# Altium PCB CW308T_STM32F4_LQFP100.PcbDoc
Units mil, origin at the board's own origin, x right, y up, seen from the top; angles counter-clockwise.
Board outline 2060 x 2540 mil, 2 copper layers (Top Layer, Bottom Layer); 19 components, 32 nets, 206 pads, 96 vias.
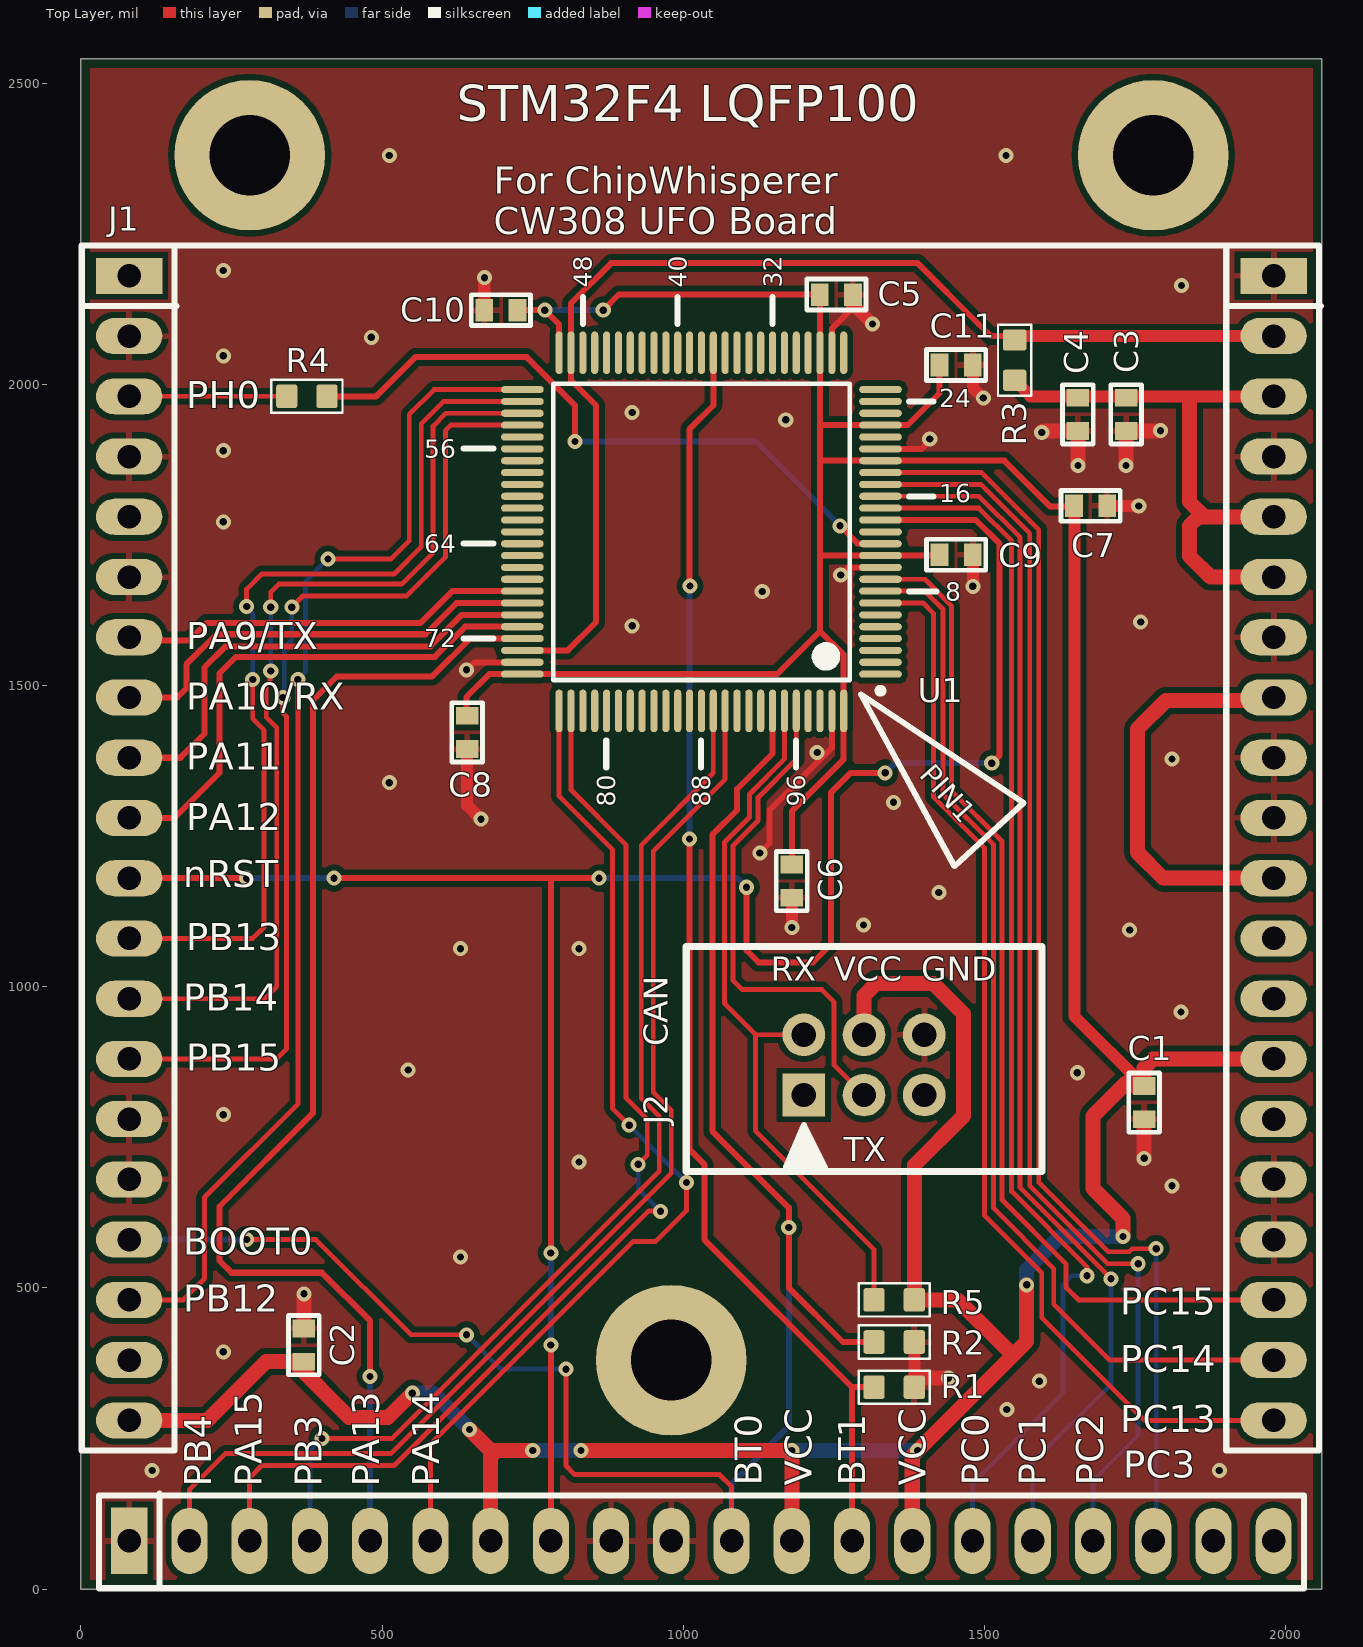
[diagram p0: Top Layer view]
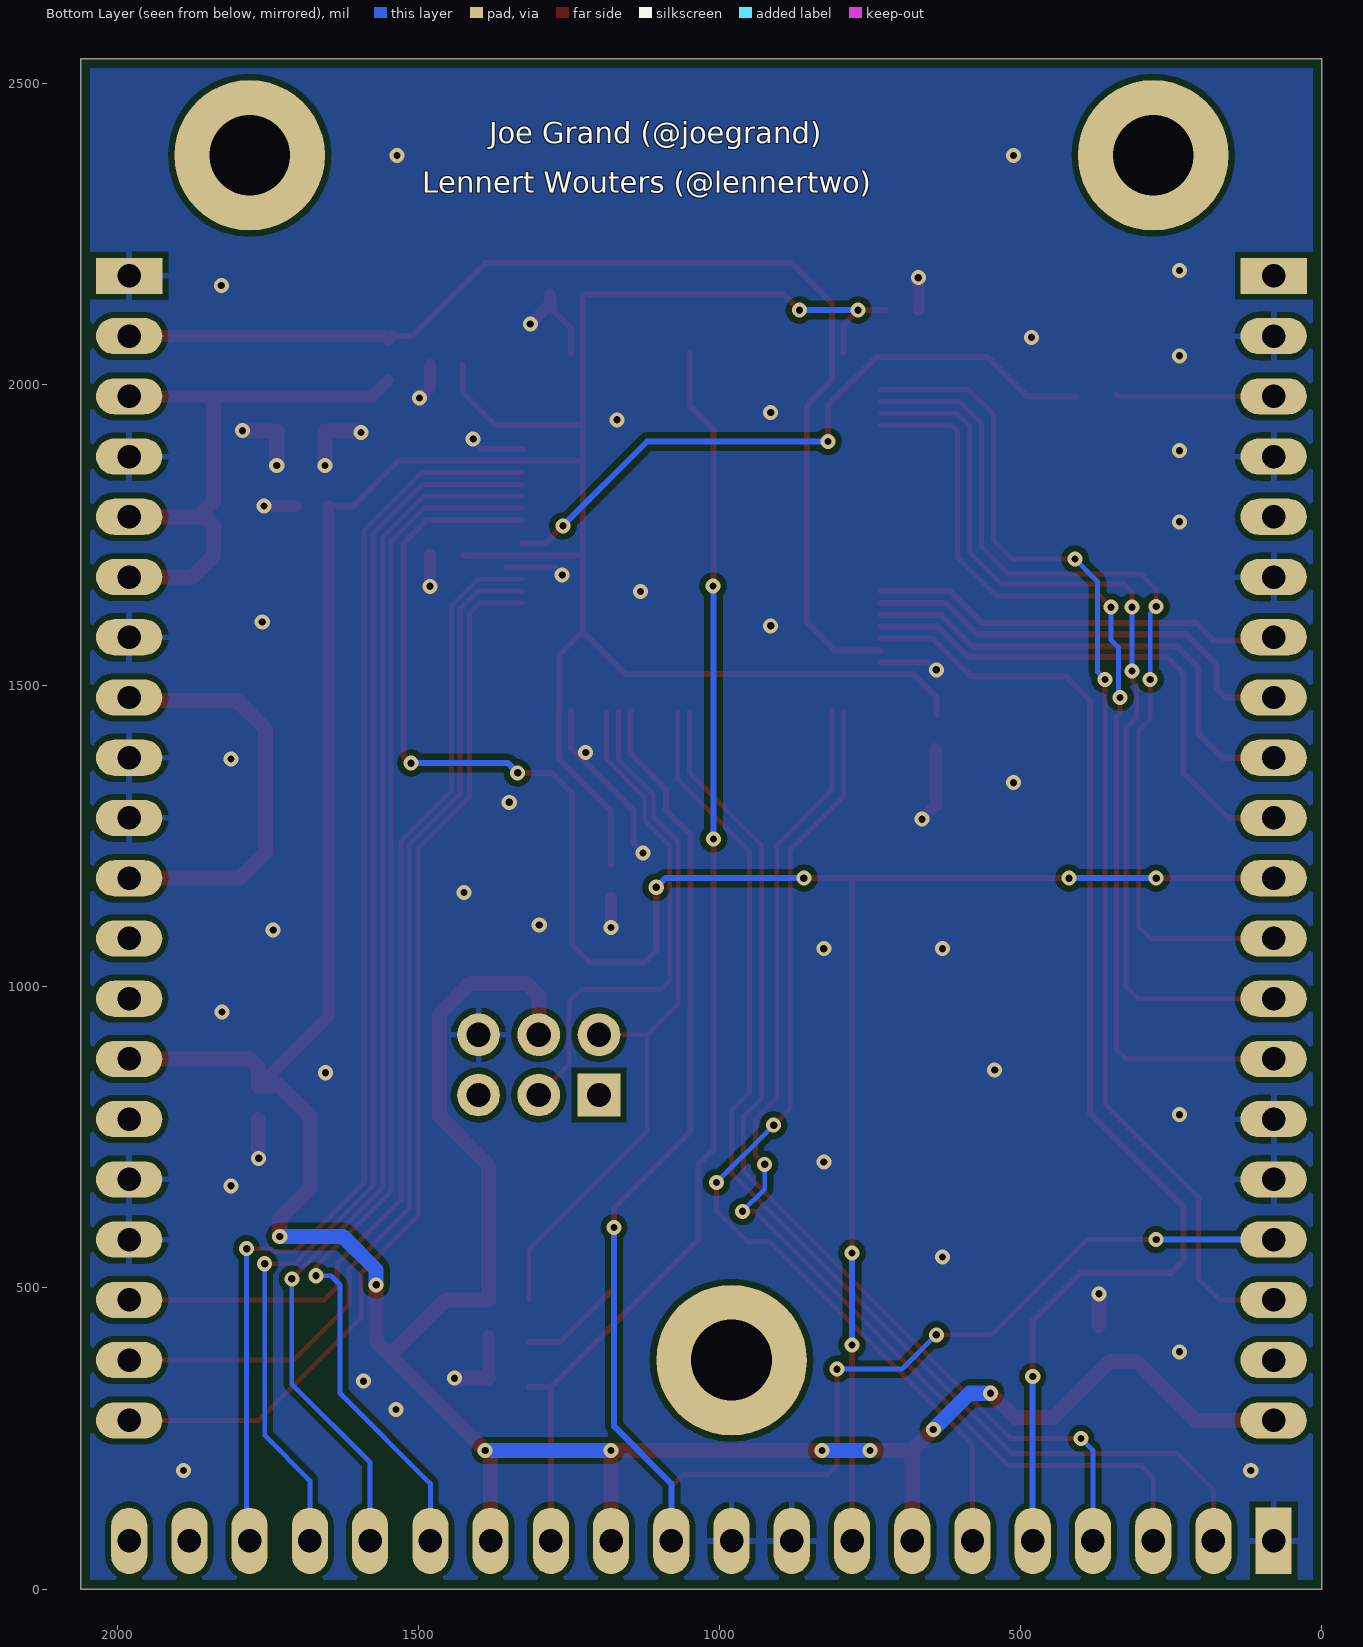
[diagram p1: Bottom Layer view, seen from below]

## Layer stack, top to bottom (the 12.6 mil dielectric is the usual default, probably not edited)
Top Solder: solder mask 0.4, Solder Resist, Dk 3.5
Top Layer: signal copper 1.4
Dielectric 1: dielectric 12.6, FR-4, Dk 4.8
Bottom Layer: signal copper 1.4
Bottom Solder: solder mask 0.4, Solder Resist, Dk 3.5

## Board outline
0,0 2060,0 2060,2540 0,2540

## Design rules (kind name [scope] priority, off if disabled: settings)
BoardOutlineClearance [All] p1: gap=15 ignorepadtopadclearanceinfootprint=FALSE except(0: Arc-SplitContinuation Track-SplitContinuation SMDPad-SplitContinuation THPad-SplitContinuation Via-SplitContinuation Fill-SplitContinuation Poly-SplitContinuation Region-SplitContinuation Text-SplitContinuation)
Clearance Clearance_1 [InPolygon] p1: gap=10 ignorepadtopadclearanceinfootprint=FALSE
Clearance [All] p2: gap=6 ignorepadtopadclearanceinfootprint=FALSE except(0: Arc-Hole Track-Hole SMDPad-Hole THPad-Hole Via-Hole Fill-Hole Poly-Hole Region-Hole Text-Hole)
HoleSize [All] p1: absolutevalues=TRUE maxlimit=200 minlimit=1 maxpercent=80.000 minpercent=20.000
MinimumSolderMaskSliver [All] p1: minsoldermaskwidth=5
PasteMaskExpansion PasteMaskExpansion_SJ [InComponent('SJ2')] p1: expansion=-200 // Disable SJ shorts
PasteMaskExpansion PasteMaskExpansion_TQFP [InComponent('U1')] p2: expansion=-99999 usepaste=FALSE
PasteMaskExpansion [All] p3: expansion=0
PlaneConnect PlaneConnect_viaDirect [IsVia] p1: planeconnectstyle=Direct reliefexpansion=20 reliefentries=4 reliefconductorwidth=10 reliefairgap=10
PlaneConnect [All] p2: planeconnectstyle=Relief reliefexpansion=20 reliefentries=4 reliefconductorwidth=10 reliefairgap=10
PolygonConnect PolygonConnect_viaDirect [All vs isVia] p1: connectstyle=Direct reliefconductorwidth=10 reliefentries=4 polygonreliefangle="90 Angle" airgapwidth=10
PolygonConnect [All] p2: connectstyle=Relief reliefconductorwidth=10 reliefentries=4 polygonreliefangle="90 Angle" airgapwidth=10
RoutingVias [All] p1: holewidth=12 width=25 viastyle="Through Hole" minholewidth=12 minwidth=25 maxholewidth=28 maxwidth=50
SilkToSilkClearance [All] p1: silktosilkclearance=5
SilkToSolderMaskClearance [IsPad] p1: minsilkscreentomaskgap=2.9 clearancetoexposedcopper=TRUE
SolderMaskExpansion U1 [InComponent('U1')] p1: expansion=2.5 istentingtop=FALSE
SolderMaskExpansion [All] p2: expansion=4 istentingtop=FALSE
SupplyNets "Schematic Supply Nets_1" [InNet('VCC')] p1: voltage=0.000
SupplyNets "Schematic Supply Nets" [InNet('GND')] p2: voltage=0.000
Width [All] p1: maxlimit=100 minlimit=6 preferedwidth=8 minimp=50.000000 maximp=50.000000 favimp=50.000000
24 further rules are at their usual default settings.

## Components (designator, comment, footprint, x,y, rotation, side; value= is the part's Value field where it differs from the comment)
C1 "100n" CAPC0603_M#1 1765,807.44 r270 top
C2 "100n" CAPC0603_M#1 370,405 r90 top
C3 "2u2" CAPC0603_M#1 1735,1950 r270 top
C4 "100n" CAPC0603_M#1 1655,1950 r270 top
C5 "100n" CAPC0603_M#2 1254,2149 r0 top
C6 "100n" CAPC0603_M#2 1180,1175 r270 top
C7 "100n" CAPC0603_M#2 1676,1798 r0 top
C8 "100n" CAPC0603_M#2 641,1422 r270 top
C9 "100n" CAPC0603_M#2 1453,1717 r0 top
C10 "100n" CAPC0603_M#2 697,2123 r180 top
C11 "100n" CAPC0603_M#1 1453,2032 r0 top
J1 "CW308_TARGETCON" CW308_TBOARD_CONN 80,2180 r0 top locked
J2 "HDR" HDR_6PIN_2ROW_SHROUD 1300,870 r90 top
R1 "10k" RESC1608X55N 1350,335 r0 top
R2 "10k" RESC1608X55N 1350,410 r0 top
R3 "10R" RESC1608X55N 1550,2040 r270 top
R4 "51R" RESC1608X55N 375,1980 r180 top value=100R
R5 "10k" RESC1608X55N 1350,480 r0 top
U1 "STM32F427VIT6" STM-LQFP100_N 1030,1755 r180 top locked

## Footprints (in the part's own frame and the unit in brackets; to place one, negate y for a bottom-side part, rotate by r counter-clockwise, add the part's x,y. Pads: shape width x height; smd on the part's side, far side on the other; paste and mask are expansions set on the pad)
CAPC0603_M#1 [mm]
  rect 0.75x0.95 smd: 1(-0.7,0) 2(0.7,0)
  silkscreen extent -1.25,-0.65 1.25,0.65, body extent -0.85,-0.45 0.85,0.45, height 0.9
CAPC0603_M#2 [mm]
  rect 0.75x0.95 smd paste-2539.97: 1(-0.7,0) 2(0.7,0)
  silkscreen extent -1.25,-0.65 1.25,0.65, body extent -0.85,-0.45 0.85,0.45, height 0.9
CW308_TBOARD_CONN [mil]
  rect 110x60 hole 39: A1(0,0) C1(1900,0)
  oval 110x60 hole 39: A2(0,-100) A3(0,-200) A4(0,-300) A5(0,-400) A6(0,-500) A7(0,-600) A8(0,-700) A9(0,-800) A10(0,-900) A11(0,-1000) A12(0,-1100) A13(0,-1200) A14(0,-1300) A15(0,-1400) A16(0,-1500) A17(0,-1600) A18(0,-1700) A19(0,-1800) A20(0,-1900) C2(1900,-100) C3(1900,-200) C4(1900,-300) C5(1900,-400) C6(1900,-500) C7(1900,-600) C8(1900,-700) C9(1900,-800) C10(1900,-900) C11(1900,-1000) C12(1900,-1100) C13(1900,-1200) C14(1900,-1300) C15(1900,-1400) C16(1900,-1500) C17(1900,-1600) C18(1900,-1700) C19(1900,-1800) C20(1900,-1900)
  rect 60x110 hole 39: B1(0,-2100)
  oval 60x110 hole 39: B2(100,-2100) B3(200,-2100) B4(300,-2100) B5(400,-2100) B6(500,-2100) B7(600,-2100) B8(700,-2100) B9(800,-2100) B10(900,-2100) B11(1000,-2100) B12(1100,-2100) B13(1200,-2100) B14(1300,-2100) B15(1400,-2100) B16(1500,-2100) B17(1600,-2100) B18(1700,-2100) B19(1800,-2100) B20(1900,-2100)
  round 250 hole 134: MH1(200,200) MH2(900,-1800) MH2(1700,200)
  silkscreen extent -79,-2179 1979,50, body extent -50,-2149 1950,50, height 48
HDR_6PIN_2ROW_SHROUD [mm] "6-pin header, male, with shroud"
  rect 1.8x1.8 hole 1.02: 1(-1.27,2.54)
  round 1.8 hole 1.02: 2(1.27,2.54) 3(-1.27,0) 4(1.27,0) 5(-1.27,-2.54) 6(1.27,-2.54)
  silkscreen extent -4.5,-7.5 5,7.5, body extent -4.44,-7.41 4.83,7.42, height 9.32
RESC1608X55N [mm] "Chip Resistor, Body 1.6x0.8mm, EIA 0603, IPC Medium Density"
  round 0.254 on Mech15: 0(0,0)
  rrect25% 0.9x1 smd: 1(-0.85,0) 2(0.85,0)
  Top Layer pour cut-out: -0.6,0.5 -0.4,0.7 0.4,0.7 0.6,0.5 0.6,-0.5 0.4,-0.7 -0.4,-0.7 -0.6,-0.5
  silkscreen extent -1.5,-0.7 1.5,0.7, body extent -0.87,-0.47 0.88,0.48, height 0.54
STM-LQFP100_N [mm] "Thin QFP, 100-Leads, Body 14x14mm, Pitch 0.5mm, IPC Medium Density"
  oval 1.8x0.3 smd: 1(-7.55,6) 2(-7.55,5.5) 3(-7.55,5) 4(-7.55,4.5) 5(-7.55,4) 6(-7.55,3.5) 7(-7.55,3) 8(-7.55,2.5) 9(-7.55,2) 10(-7.55,1.5) 11(-7.55,1) 12(-7.55,0.5) 13(-7.55,0) 14(-7.55,-0.5) 15(-7.55,-1) 16(-7.55,-1.5) 17(-7.55,-2) 18(-7.55,-2.5) 19(-7.55,-3) 20(-7.55,-3.5) 21(-7.55,-4) 22(-7.55,-4.5) 23(-7.55,-5) 24(-7.55,-5.5) 25(-7.55,-6) 51(7.55,-6) 52(7.55,-5.5) 53(7.55,-5) 54(7.55,-4.5) 55(7.55,-4) 56(7.55,-3.5) 57(7.55,-3) 58(7.55,-2.5) 59(7.55,-2) 60(7.55,-1.5) 61(7.55,-1) 62(7.55,-0.5) 63(7.55,0) 64(7.55,0.5) 65(7.55,1) 66(7.55,1.5) 67(7.55,2) 68(7.55,2.5) 69(7.55,3) 70(7.55,3.5) 71(7.55,4) 72(7.55,4.5) 73(7.55,5) 74(7.55,5.5) 75(7.55,6)
  oval 0.3x1.8 smd: 26(-6,-7.55) 27(-5.5,-7.55) 28(-5,-7.55) 29(-4.5,-7.55) 30(-4,-7.55) 31(-3.5,-7.55) 32(-3,-7.55) 33(-2.5,-7.55) 34(-2,-7.55) 35(-1.5,-7.55) 36(-1,-7.55) 37(-0.5,-7.55) 38(0,-7.55) 39(0.5,-7.55) 40(1,-7.55) 41(1.5,-7.55) 42(2,-7.55) 43(2.5,-7.55) 44(3,-7.55) 45(3.5,-7.55) 46(4,-7.55) 47(4.5,-7.55) 48(5,-7.55) 49(5.5,-7.55) 50(6,-7.55) 76(6,7.55) 77(5.5,7.55) 78(5,7.55) 79(4.5,7.55) 80(4,7.55) 81(3.5,7.55) 82(3,7.55) 83(2.5,7.55) 84(2,7.55) 85(1.5,7.55) 86(1,7.55) 87(0.5,7.55) 88(0,7.55) 89(-0.5,7.55) 90(-1,7.55) 91(-1.5,7.55) 92(-2,7.55) 93(-2.5,7.55) 94(-3,7.55) 95(-3.5,7.55) 96(-4,7.55) 97(-4.5,7.55) 98(-5,7.55) 99(-5.5,7.55) 100(-6,7.55)
  silkscreen extent -7.68,-6.25 6.25,6.82, body extent -7,-7 7,7, height 1.6

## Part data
C1 C2 C4 C5 C6 C7 C8 C9 C10 C11: library part CCHIP-100n-0603, "100n, 0603", Case-EIA=0603, Case-Metric=1608
C3: library part CCHIP-2u2-0603, "2u2, 0603", Case-EIA=0603, Case-Metric=1608
J1: library part CW308_TBOARD, "CW308 \"Standard\" Target Board Connector"
J2: library part HDR_6PIN_2ROW_SHROUD, "HDR, Male, 6-Pin, 2 Row, Shrouded", Manufacture 1="FCI Connectors", Manufacture Part Number 1=75869-131LF, Supplier Part Number 1=609-2845-ND
R1 R2 R5: library part RCHIP-10K-0603, "10k res, 0603, 1%, 1/10W", Case-EIA=0603, Case-Metric=1608, Manufacture 1=Yageo, Manufacture Part Number 1=RC0603FR-0710KL, Rated Power=0.1W, Rated Voltage=75VDC, Supplier Part Number 1=311-10.0KHRCT-ND, Temperature Range="-55C to 155C", Tolerance=1%
R3: library part RCHIP-10R-0603, "10R res, 0603, 1%, 1/10W", Case-EIA=0603, Case-Metric=1608, Manufacture 1=Yageo, Manufacture Part Number 1=RC0603FR-0710RL, Rated Power=0.1W, Rated Voltage=75VDC, Supplier Part Number 1=311-10.0HRCT-ND, Temperature Range="-55C to 155C", Tolerance=1%
R4: library part RCHIP-100R-0603, "100R res, 0603, 1%, 1/10W", Case-EIA=0603, Case-Metric=1608, Manufacture 1=Yageo, Manufacture Part Number 1=RC0603FR-07100RL, Rated Power=0.1W, Rated Voltage=75VDC, Supplier Part Number 1=311-100HRCT-ND, Temperature Range="-55C to 155C", Tolerance=1%
U1: "ARM Cortex-M4 32-bit MCU+FPU, 210 DMIPS, 2048 kB Flash, 256 kB Internal RAM, 82 I/Os, 100-pin LQFP, -40 to 85 degC, Tray", I/Os (High Current)=82, Manufacturer=STMicroelectronics, Operating Frequency(F) (Processor speed) (MHz)=168, Supplier Part Number 1=497-14049-ND, Supply Voltage(Vcc) max (V)=3.6, Supply Voltage(Vcc) min (V)=1.8

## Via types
v1: diameter 25, hole 12, Top Layer to Bottom Layer, tented both sides, 96 vias

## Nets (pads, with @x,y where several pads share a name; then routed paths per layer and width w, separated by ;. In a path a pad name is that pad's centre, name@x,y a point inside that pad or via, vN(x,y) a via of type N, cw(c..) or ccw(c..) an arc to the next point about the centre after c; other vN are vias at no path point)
BOOT0: J1.A17 J1.B11 R2.1 U1.94 | length 3143.5
  Top Layer w8: v1(275,580) 390,580 548,422 v1(640,422) ; v1(805,365) 805,205 820,190 1060,190 1080,170 J1.B11
  Top Layer w10: U1.94 1148.11,1387.11 1089,1328 1089,1293 1048,1252 1048,760 1175,633 v1(1175,600) 1175,500 1265,410 R2.1
  Bottom Layer w8: v1(640,422) 697,365 v1(805,365)
  Bottom Layer w10: J1.A17 v1(275,580) ; J1.B11 1080,175 1175,270 v1(1175,600)
BOOT1: J1.B13 R1.1 U1.37 | length 2138.1
  Top Layer w10: v1(1010,1245) 1010,730 1035,705 1035,580 1280,335 ; v1(1011,1665) 1010,1666 1010,1925 1050,1965 1050,2051.93 U1.37 ; J1.B13 1280,335 ; R1.1 1280,335
  Bottom Layer w10: v1(1010,1245) 1010,1664 v1(1011,1665)
CAN_RX: J2.2 R5.1 U1.95 | length 1201.6
  Top Layer w8: U1.95 1167.8,1377.59 1110,1319.8 1110,1281.62 1068.5,1240.12 1068.5,971.5 1120,920 ; J2.2 1120,920 ; R5.1 1316.54,563.46 1120,760 1120,920
CAN_TX: J2.3 U1.96 | length 848.9
  Top Layer w8: U1.96 1187.48,1377.48 1124,1314 1124,1275.82 1082.5,1234.32 1082.5,1010 1097.5,995 1230,995 1250,975 1250,870 J2.3
CLKI: R4.1 U1.12 | length 1109.1
  Top Layer w10: R4.1 490,1980 555,2045 740,2045 820,1965 v1(820,1905) ; v1(1260,1765) 1289.34,1735.66 1326.9,1735.66 U1.12
  Bottom Layer w10: v1(820,1905) 1120,1905 v1(1260,1765)
CS: J1.A18 U1.51 | length 1981.7
  Top Layer w8: J1.A18 170,480 205,515 205,650 360,805 v1(360,1510) ; v1(410,1710) 515,1710 545,1740 545,1950 586.22,1991.22 U1.51
  Bottom Layer w8: v1(360,1510) 372.5,1522.5 372.5,1672.5 v1(410,1710)
GND: C1.2 C2.2 C3.2 C4.2 C5.2 C6.2 C7.2 C8.2 C9.2 C10.2 C11.2 J1.A2 J1.A4 J1.A6 J1.A15 J1.A16 J1.B1 J1.B9 J1.B10 J1.C1 J1.C4 J1.C7 J1.C9 J1.C10 J1.C16 J1.C17 J2.6 R1.2 R2.2 U1.10 U1.20 U1.27 U1.74 U1.99 | length 1617.8
  Top Layer w10: v1(640,1526) 640.89,1526 653.36,1538.46 U1.74 ; v1(1127,1222) 1142.95,1237.95 1142.95,1292.95 1246.54,1396.54 U1.99 ; U1.27 1246.88,2052.59 1246.88,2092.88 1275.16,2121.16 1275.16,2132.44 1275.16,2142.6 C5.2 ; v1@1262.14,1683.54 1274.6,1696 U1.10@1354,1696 ; U1.20 1395.64,1892.8 1409,1906.15 v1(1409,1909)
  Top Layer w20: C8.2 641,1301 v1(664,1278) ; C10.2 669.44,2176.44 v1(670,2177) ; v1(1180,1098) C6.2 ; C5.2 1281.56,2132.44 v1(1314,2100) ; R1.2@1383.46,350 R2.2@1383.46,420 ; v1(1480.56,1664.56) C9.2 ; C11.2 1480.56,1994.44 v1(1498,1977) ; C7.2 v1(1756,1798)
  Top Layer w25: C2.2@370,437.56 v1(370,490) ; R1.2@1383.46,350 v1(1440,350) ; v1(1595,1920) 1597.44,1922.44 C4.2 v1(1655,1865) ; v1(1735,1865) C3.2 1791.44,1922.44 v1(1792,1923) ; v1(1765,715) C1.2
  other v1: 118.11,196.85 1889.76,196.85 1537,298 1591,345 236.22,393.7 629.92,551.18 1811.02,669.29 826.77,708.66 236.22,787.4 1654,857 543.13,861.48 1826,958 629.92,1062.99 826.77,1062.99 1741,1094 1299.21,1102.36 1424.13,1156.48 1349,1306 511.81,1338.58 1811.02,1377.95 1222.13,1388.48 915,1599 1759.13,1605.48 1131,1656 1261.24,1683.54 236.22,1771.65 236.22,1889.76 1170,1941 915,1953 236.22,2047.24 482,2078 1827,2164 236.22,2189 511.81,2380 1535.43,2380
GPIO3: J1.A9 U1.70 | length 815.4
  Top Layer w10: J1.A9 165,1380 205,1420 205,1530 240,1565 580.15,1565 632.36,1617.2 U1.70
GPIO4: J1.A10 U1.71 | length 880.9
  Top Layer w10: J1.A10 155,1280 230,1355 230,1520 257.34,1547.34 587.47,1547.34 637.65,1597.52 U1.71
LED1: J1.C18 U1.9 | length 1699.7
  Top Layer w8: U1.9 1401.17,1676.26 1445,1632.43 1445,1325 1529,1241 1529,646 1635,540 1635,501 1656,480 J1.C18
LED2: J1.C19 U1.8 | length 1749.5
  Top Layer w8: U1.8 1401.05,1656.57 1431,1626.63 1431,1319.2 1515,1235.2 1515,632 1615,532 1615,473 1708,380 J1.C19
LED3: J1.C20 U1.7 | length 1794.7
  Top Layer w8: U1.7 1398.11,1636.89 1415,1620 1415,1315 1500,1230 1500,620 1595,525 1595,450 1765,280 J1.C20
MISO: J1.A13 U1.53 | length 1586.5
  Top Layer w8: J1.A13 305,980 325,1000 325,1430 307.5,1447.5 307.5,1500 313.85,1506.35 313.85,1522.69 v1(315,1523.84) ; v1(315,1630) 315,1655 328.27,1668.27 532.3,1668.27 584.52,1720.48 584.52,1930.48 605.89,1951.85 U1.53
  Bottom Layer w8: v1(315,1523.84) 315,1620 320,1625 v1(315,1630)
MOSI: J1.A14 U1.54 | length 1648.3
  Top Layer w8: J1.A14 325,880 341,896 341,1449 335,1455 v1(335,1480) ; v1@345,1635 v1(350,1630) 368.58,1648.58 540.46,1648.58 605,1713.12 605,1923.12 614.04,1932.17 U1.54
  Bottom Layer w8: v1(335,1480) 337.5,1482.5 337.5,1562.5 350,1575 v1(350,1630)
NetC3_1: C3.1 C4.1 J1.C3 J1.C5 J1.C6 R3.2 | length 998.1
  Top Layer w20: R3.2 1576.54,1980 1840,1980 J1.C3
  Top Layer w25: 1840,1976 1840,1805 1865,1780 ; J1.C6 1875,1680 1840,1715 1840,1765 1855,1780 1865,1780 ; J1.C5 1865,1780
NetJ1_A3: J1.A3 R4.2 | length 263.6
  Top Layer w8: J1.A3 336.54,1980 R4.2@341.54,1985
NetJ1_C2: J1.C2 R3.1 U1.49 U1.73 | length 1937.9
  Top Layer w10: U1.73 808.15,1558.15 855,1605 855,1965 813.46,2006.54 U1.49 813.46,2134.46 880,2201 1389,2201 1490,2100 1510,2080 R3.1@1543.46,2080
  Top Layer w20: R3.1@1543.46,2080 R3.1 1556.54,2080 J1.C2
NetJ1_C8: J1.C8 J1.C11 | length 696.6
  Top Layer w25: J1.C11 1796.64,1180 1754,1222.64 1754,1428 1801,1475 1975,1475 J1.C8
nRST: J1.A11 J1.B8 U1.14 | length 3519.8
  Top Layer w10: J1.A11 v1(275,1180) ; v1(420,1180) 780,1180 ; J1.B8 v1(780,405) ; v1(780,558) 780,1180 ; v1(860,1180) 780,1180 ; v1(1105,1165) 1105,1060 1125,1040 1215,1040 1245,1070 1245,1322 1278,1355 v1(1335,1355) ; U1.14 1485.31,1774.68 1525,1735 1525,1384.36 1512,1371.36 v1(1512,1371)
  Bottom Layer w10: v1(275,1180) v1(420,1180) ; v1(780,405) v1(780,558) ; v1(860,1180) 1090,1180 v1(1105,1165) ; v1(1335,1355) 1351,1371 v1(1512,1371)
PC0: J1.B15 U1.15 | length 2045.4
  Top Layer w8: U1.15 1490.63,1794.37 1545,1740 1545,660 1670,535 v1(1670,520)
  Bottom Layer w8: J1.B15 1480,175 1630,325 1630,505 1645,520 v1(1670,520)
PC1: J1.B16 U1.16 | length 2042.2
  Top Layer w8: U1.16 1490.74,1814.06 1559,1745.8 1559,666 v1(1710,515)
  Bottom Layer w8: J1.B16 1580,210 1710,340 v1(1710,515)
PC2: J1.B17 U1.17 | length 2088.9
  Top Layer w8: U1.17 1493.69,1833.74 1575,1752.43 1575,669.8 1704.8,540 v1(1755,540)
  Bottom Layer w8: J1.B17 1680,180 1755,255 v1(1755,540)
PC3: J1.B18 U1.18 | length 2117.4
  Top Layer w8: U1.18 1495.21,1853.43 1590,1758.64 1590,675 1705,560 1740,560 1745,565 v1(1785,565)
  Bottom Layer w8: J1.B18 1785,85 v1(1785,565)
RX: J1.A8 U1.69 | length 741.2
  Top Layer w10: J1.A8 160,1480 175,1495 175,1535 225,1585 571.87,1585 623.76,1636.89 U1.69
SCK: J1.A12 U1.52 | length 1511.5
  Top Layer w8: J1.A12 285,1080 304,1099 304,1426 285,1445 v1(285,1510) ; v1(275,1631) 275,1660 300,1685 520,1685 565,1730 565,1934.63 601.91,1971.54 U1.52
  Bottom Layer w8: v1(275,1631) 275,1630 285,1620 v1(285,1510)
TCK: J1.B6 U1.76 | length 1663
  Top Layer w8: J1.B6 580,240 917,577 954,577 1005,628 v1(1005,675) ; U1.76 793.78,1316.22 882.5,1227.5 882.5,797.5 v1(910,770)
  Bottom Layer w8: v1(910,770) v1(1005,675)
TDI: J1.B3 U1.77 | length 1875.4
  Top Layer w8: J1.B3 280,185 300,205 520,205 942.68,627.68 961.32,627.68 v1(962,627) ; U1.77 813.46,1326.54 905,1235 905,815 940,780 940,720 v1(925,705)
  Bottom Layer w8: v1(925,705) 925,664 v1(962,627)
TDO: J1.B4 U1.89 | length 1748.4
  Top Layer w8: v1(400,250) 516.82,250 960,693.18 960,785 930,815 930,1235 1049.68,1354.68 U1.89
  Bottom Layer w8: J1.B4 380,230 v1(400,250)
TMS: J1.B5 U1.72 | length 2041
  Top Layer w10: v1(480,353) 480,445 400,525 250,525 230,545 230,635 385,790 385,1475 425,1515 583,1515 645.83,1577.83 U1.72
  Bottom Layer w10: J1.B5 v1(480,353)
TRST: J1.B2 U1.90 | length 1932.1
  Top Layer w8: J1.B2 180,165 240,225 515,225 980,690 980,795 950,825 950,1225 1069.37,1344.37 U1.90
TX: J1.A7 U1.68 | length 688.6
  Top Layer w10: J1.A7 85,1575 180,1575 209,1604 564,1604 616.57,1656.57 U1.68
VCC: C1.1 C2.1 C5.1 C6.1 C7.1 C8.1 C9.1 C10.1 C11.1 J1.A20 J1.B7 J1.B12 J1.B14 J1.C14 J2.4 R5.2 U1.11 U1.19 U1.22 U1.28 U1.50 U1.75 U1.100 | length 8191.9
  Top Layer w10: C8.1@640,1450.56 640,1481 677.78,1518.78 U1.75 1155.48,1518.78 1226.85,1590.15 ; C10.1 v1(770,2123) 793.78,2099.22 U1.50 ; v1(867,2123) 893,2149 C5.1 1226.85,2148.59 U1.28 1226.85,1590.15 ; C6.1 1180,1291 1266.22,1377.22 U1.100 1266,1457.98 1266,1551 1226.85,1590.15 ; 1227,1932.17 U1.22 1372.17,1932.17 1425.44,1985.44 C11.1 ; 1228,1715.63 U1.11 1424.07,1715.63 C9.1 ; 1228,1873.11 U1.19 1532.89,1873.11 1609,1797 C7.1@1647.44,1797
  Top Layer w20: C7.1@1649,1798 1649,951 C1.1
  Top Layer w25: J1.A20 210,280 307.44,377.44 352.56,377.44 445,285 510,285 v1(550,325) ; v1(645,265) 680,230 690,230 ; J1.B7 680,220 690,230 ; v1(750,230) 690,230 ; v1(830,230) v1(1180,230) J1.B12 ; J2.4 1300,985 1320,1005 1415,1005 1465,955 1465,785 1383.46,703.46 R5.2 1455,480 1547,388 ; J1.B14 1380,221 v1(1389,230) 1547,388 ; v1(1570,505) 1570,411 1547,388 ; v1(1730,585) 1730,615 1680,665 1680,785 1735,840 1740,835 C1.1 1765,865 1780,880 J1.C14
  Bottom Layer w10: v1(770,2123) v1(867,2123)
  Bottom Layer w25: v1(550,325) 585,325 v1(645,265) ; v1(750,230) v1(830,230) ; v1(1180,230) v1(1389,230) ; v1(1570,505) 1570,530 1625,585 v1(1730,585)
pads on no net: J1.A1 J1.A5 J1.A19 J1.B19 J1.B20 J1.C12 J1.C13 J1.C15 J1.MH1 J1.MH2 J2.1 J2.5 R1.0 R2.0 R3.0 R4.0 R5.0 U1.1 U1.2 U1.3 U1.4 U1.5 U1.6 U1.13 U1.21 U1.23 U1.24 U1.25 U1.26 U1.29 U1.30 U1.31 U1.32 U1.33 U1.34 U1.35 U1.36 U1.38 U1.39 U1.40 U1.41 U1.42 U1.43 U1.44 U1.45 U1.46 U1.47 U1.48 U1.55 U1.56 U1.57 U1.58 U1.59 U1.60 U1.61 U1.62 U1.63 U1.64 U1.65 U1.66 U1.67 U1.78 U1.79 U1.80 U1.81 U1.82 U1.83 U1.84 U1.85 U1.86 U1.87 U1.88 U1.91 U1.92 U1.93 U1.97 U1.98

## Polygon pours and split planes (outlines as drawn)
GND on Bottom Layer "GNDBOT" (solid, remove dead copper, pour order 0): -35,2580 -75,2540 -75,-70 2095,-70 2175,10 2175,2675
GND on Top Layer "Top Layer-GND" (solid, remove dead copper, pour order 2): -30,2660 -10,2640 2100,2640 2100,-25 2120,-45 2100,-65 -50,-65

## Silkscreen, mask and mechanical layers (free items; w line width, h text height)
Top Overlay:
  lines w10: 155,2230 1901.26,2230 ; 635,1578.04 685,1578.04 ; 635,1735.52 685,1735.52 ; 635,1893 685,1893 ; 833.04,2100 833.04,2145 ; 872,1364 872,1409 ; 990.52,2100 990.52,2145 ; 1029.48,1364 1029.48,1409 ; 1148,2100 1148,2145 ; 1186.96,1364 1186.96,1409 ; 1205,730 1195,710 1210,715 1205,740 1182,705 1215,710 1200,770 ; 1375,1656 1420,1656 ; 1375,1814 1415,1814 ; 1375,1971.48 1415,1971.48 ; 1200,770 1200,750 1180,700 1225,705 1200,770 ; 1200,770 1235,700 1170,700 1200,770 ; 1295,1485 1565,1305 1450,1200 1295,1485
  text "STM32F4 LQFP100" at 624,2437 h60
  text "For ChipWhisperer / CW308 UFO Board" at 685,2249 h45
  text "48" at 848.04,2160 h30 r90
  text "40" at 1005.52,2160 h30 r90
  text "32" at 1163,2160 h30 r90
  text "24" at 1425,1961.48 h30
  text "PH0" at 175,1960 h45
  text "56" at 570,1878 h30
  text "16" at 1425,1804 h30
  text "64" at 570,1720.52 h30
  text "8" at 1435,1641 h30
  text "72" at 570,1563.04 h30
  text "PA9/TX" at 175,1560 h45
  text "PA10/RX" at 175,1460 h45
  text "PA11" at 175,1360 h45
  text "PIN1" at 1390,1350 h35 r311.73
  text "80" at 887,1299 h30 r90
  text "88" at 1044.48,1299 h30 r90
  text "96" at 1201.96,1299 h30 r90
  text "PA12" at 175,1260 h45
  text "nRST" at 170,1165 h45
  text "PB13" at 175,1060 h45
  text "RX" at 1145,1010 h40
  text "VCC" at 1250,1010 h40
  text "GND" at 1395,1010 h40
  text "PB14" at 170,960 h45
  text "CAN" at 974,901 h40 r90
  text "PB15" at 175,860 h45
  text "TX" at 1266,710 h40
  text "BOOT0" at 170,555 h45
  text "PB12" at 170,460 h45
  text "PC15" at 1725,455 h45
  text "PC14" at 1725,360 h45
  text "PC13" at 1725,260 h45
  text "PC3" at 1730,185 h45
  text "BT0" at 1130,171 h45 r90
  text "VCC" at 1213,171 h45 r90
  text "BT1" at 1302,171 h45 r90
  text "VCC" at 1402,171 h45 r90
  text "PC0" at 1507,171 h45 r90
  text "PC1" at 1602,171 h45 r90
  text "PC2" at 1697,171 h45 r90
  text "PB4" at 216,170 h45 r90
  text "PA15" at 300,170 h45 r90
  text "PB3" at 400,170 h45 r90
  text "PA13" at 495,170 h45 r90
  text "PA14" at 595,170 h45 r90
Bottom Overlay:
  text "Joe Grand (@joegrand)" at 1382.5,2400 h35
  text "Lennert Wouters (@lennertwo)" at 1493.3,2318 h35
Mechanical 1:
  the board outline again, w10

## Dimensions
2060,-30 to 0,-30 on Drill Drawing
-30,0 to -45,2540 on Drill Drawing
-30,0 to -45,2540 on Drill Drawing
0,-40 to 2060,-40 on Drill Drawing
